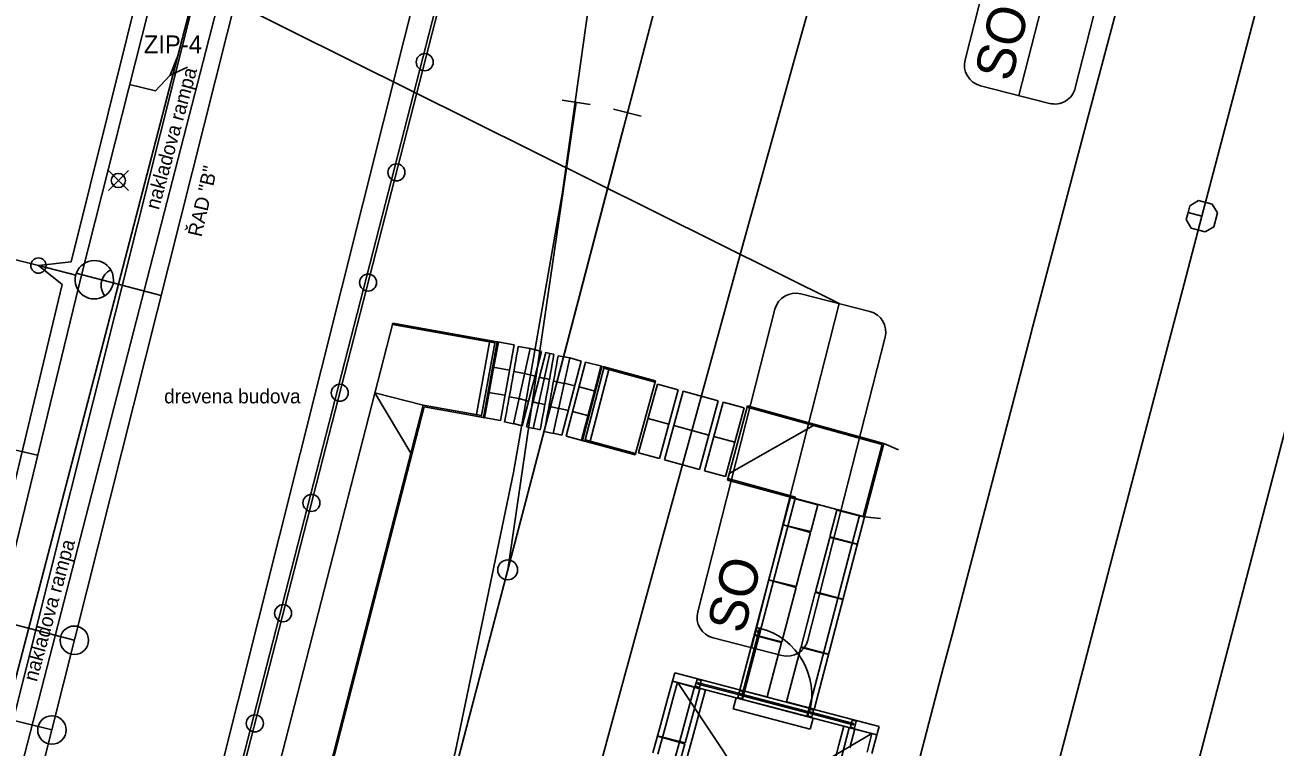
# Model space of a CAD drawing. Extents: x -733601 to -733291, y -1137892 to -1137187.
# Drawn here: x -733445.37 to -733401.43, y -1137582.33 to -1137556.95 of the extents above; entities that cross this region are included whole.
import ezdxf

# ---------------------------------------------------------------- set-up
doc = ezdxf.new("R2010")
doc.units = 0
for name, color, linetype in [('Default', 7, 'Continuous'), ('SIT_PROJ', 7, 'Continuous'), ('SIT_PUV_BUS', 7, 'Continuous'), ('SIT_PUV_ZELEZNICE', 7, 'Continuous')]:
    doc.layers.add(name, color=color, linetype=linetype)

# ---------------------------------------------------------------- blocks, each defined once
blk = doc.blocks.new('novy_s_2r')
at = {"layer": 'Default'}
for p in [(502.569, 387.82), (502.559, 384.813)]:
    blk.add_line(p, (502.564, 386.316), dxfattribs=at)
blk.add_circle((502.564, 386.316), 0.298, dxfattribs=at)
blk.add_circle((502.564, 386.316), 0.298, dxfattribs=at)
blk.add_circle((502.564, 386.316), 0.298, dxfattribs=at)
blk.add_circle((502.564, 386.316), 0.298, dxfattribs=at)
for centre, radius, start, end in [((502.571, 388.57), 0.75, 46.9837, 135.4673), ((502.571, 388.57), 0.75, 46.9837, 135.4673), ((502.571, 388.57), 0.75, 135.4683, 46.9828), ((502.55, 389.547), 0.684, 221.2842, 321.1668), ((502.55, 389.547), 0.684, 221.2842, 321.1668), ((502.556, 384.063), 0.75, 315.4683, 226.9828), ((502.577, 383.086), 0.684, 41.2842, 141.1668), ((502.577, 383.086), 0.684, 41.2842, 141.1668), ((502.556, 384.063), 0.75, 226.9837, 315.4673), ((502.556, 384.063), 0.75, 226.9837, 315.4673)]:
    blk.add_arc(centre, radius, start, end, dxfattribs=at)
blk = doc.blocks.new('VY1')
at = {"layer": 'Default'}
for q in [(-50, 275), (50, 275), (0, 0)]:
    blk.add_line((0, 150), q, dxfattribs=at)
blk = doc.blocks.new('POINT_DISPLAY')
at = {"layer": 'Default'}
for p, q in [((-0.7, -0.7), (0.7, 0.7)), ((-0.7, 0.7), (0.7, -0.7))]:
    blk.add_line(p, q, dxfattribs=at)
blk.add_circle((0, 0), 0.5, dxfattribs=at)
blk = doc.blocks.new('vytyc_bod_MP')
at = {"layer": 'Default'}
blk.add_blockref('POINT_DISPLAY', (0, 0), dxfattribs=at)
blk = doc.blocks.new('T_PS_1_1_6')
at = {"layer": 'Default'}
blk.add_line((-12.486, 3.717), (12.486, 3.717), dxfattribs=at)
for points in [[(10.986, 8), (-10.986, 8)], [(-12.486, 6.5), (-12.486, 1.5)], [(12.486, 1.5), (12.486, 6.5)], [(-10.986, 0), (10.986, 0)]]:
    blk.add_lwpolyline(points, dxfattribs=at)
for centre, start, end in [((-10.986, 6.5), 90, 180), ((10.986, 6.5), 0, 90), ((-10.986, 1.5), 180, 270), ((10.986, 1.5), 270, 360)]:
    blk.add_arc(centre, 1.5, start, end, dxfattribs=at)
blk.add_text('SO', height=2.7, dxfattribs=at).set_placement((-11.75, 4.466))
blk = doc.blocks.new('T_PS_1_1_7')
at = {"layer": 'Default'}
blk.add_line((-12.486, 3.717), (12.486, 3.717), dxfattribs=at)
for points in [[(10.986, 8), (-10.986, 8)], [(-12.486, 6.5), (-12.486, 1.5)], [(12.486, 1.5), (12.486, 6.5)], [(-10.986, 0), (10.986, 0)]]:
    blk.add_lwpolyline(points, dxfattribs=at)
for centre, start, end in [((-10.986, 6.5), 90, 180), ((10.986, 6.5), 0, 90), ((-10.986, 1.5), 180, 270), ((10.986, 1.5), 270, 360)]:
    blk.add_arc(centre, 1.5, start, end, dxfattribs=at)
blk.add_text('SO', height=2.7, dxfattribs=at).set_placement((-11.75, 4.466))

msp = doc.modelspace()

# ---------------------------------------------------------------- linework, layer by layer
at = {"layer": 'SIT_PROJ'}
msp.add_line((-733440.281, -1137593.122), (-733430.325, -1137554.381), dxfattribs=at)
for points in [[(-733457.917, -1137622.364), (-733458.777, -1137620.095), (-733456.339, -1137614.218), (-733457.273, -1137613.333), (-733455.913, -1137612.939), (-733454.69, -1137608.9), (-733452.562, -1137600.661), (-733449.967, -1137590.732), (-733451.007, -1137589.721), (-733449.679, -1137589.475), (-733444.067, -1137566.075), (-733444.902, -1137565.405), (-733443.754, -1137565.269), (-733437.875, -1137541.673), (-733438.793, -1137541.042), (-733437.71, -1137541.027), (-733436.525, -1137536.63), (-733452.133, -1137532.662), (-733452.807, -1137531.541)], [(-733456.299, -1137623.235), (-733433.573, -1137532.72)], [(-733432.51, -1137534.385), (-733444.427, -1137581.731), (-733459.039, -1137578.132)], [(-733429.102, -1137545.713), (-733449.631, -1137627.477)], [(-733457.917, -1137622.364), (-733458.523, -1137621.757), (-733455.851, -1137614.377), (-733455.422, -1137613.019), (-733451.725, -1137599.481), (-733449.522, -1137590.912), (-733449.164, -1137589.482), (-733443.392, -1137565.741), (-733438.875, -1137547.904)], [(-733440.387, -1137554.973), (-733416.748, -1137566.741), (-733416.748, -1137566.741)], [(-733441.694, -1137559.038), (-733440.78, -1137559.259)], [(-733443.578, -1137565.675), (-733440.587, -1137566.455)], [(-733448.861, -1137571.168), (-733444.931, -1137572.072)], [(-733446.608, -1137577.804), (-733443.64, -1137578.577)], [(-733454.604, -1137622.264), (-733444.427, -1137581.731)]]:
    msp.add_lwpolyline(points, dxfattribs=at)
for centre, radius in [((-733431.321, -1137558.255), 0.3), ((-733432.316, -1137562.129), 0.3), ((-733433.312, -1137566.003), 0.3), ((-733434.307, -1137569.877), 0.3), ((-733435.303, -1137573.751), 0.3), ((-733436.299, -1137577.626), 0.3), ((-733443.64, -1137578.578), 0.5), ((-733444.427, -1137581.732), 0.5), ((-733437.294, -1137581.5), 0.3)]:
    msp.add_circle(centre, radius, dxfattribs=at)
at = {"layer": 'SIT_PUV_BUS'}
for p, q in [((-733437.84, -1137549.69), (-733442.47, -1137567.55)), ((-733445.62, -1137583.47), (-733437, -1137550.03)), ((-733429.79, -1137551.88), (-733440.4, -1137593.2)), ((-733442.47, -1137567.55), (-733446.56, -1137583.19))]:
    msp.add_line(p, q, dxfattribs=at)
at = {"layer": 'SIT_PUV_ZELEZNICE'}
for p, q in [((-733404.487, -1137563.543), (-733404.423, -1137563.301)), ((-733404.423, -1137563.301), (-733404.117, -1137563.123)), ((-733404.117, -1137563.123), (-733403.634, -1137563.25)), ((-733403.634, -1137563.25), (-733403.456, -1137563.556)), ((-733404.55, -1137563.785), (-733404.487, -1137563.543)), ((-733404.003, -1137563.67), (-733404.487, -1137563.543)), ((-733403.456, -1137563.556), (-733403.583, -1137564.039)), ((-733404.372, -1137564.09), (-733404.55, -1137563.785)), ((-733403.889, -1137564.217), (-733404.372, -1137564.09)), ((-733403.583, -1137564.039), (-733403.889, -1137564.217)), ((-733437.941, -1137588.784), (-733432.439, -1137567.425)), ((-733428.859, -1137568.124), (-733432.452, -1137567.473)), ((-733428.769, -1137568.089), (-733432.439, -1137567.425)), ((-733429.028, -1137568.042), (-733429.509, -1137570.699)), ((-733428.85, -1137568.074), (-733429.332, -1137570.731)), ((-733428.769, -1137568.089), (-733429.25, -1137570.746)), ((-733428.757, -1137568.091), (-733429.239, -1137570.748)), ((-733429.028, -1137568.042), (-733428.732, -1137568.096)), ((-733428.769, -1137568.089), (-733428.85, -1137568.074)), ((-733428.757, -1137568.091), (-733428.178, -1137568.196)), ((-733428.178, -1137568.196), (-733428.66, -1137570.853)), ((-733428.205, -1137570.973), (-733427.618, -1137568.321)), ((-733427.618, -1137568.321), (-733428.031, -1137568.248)), ((-733427.213, -1137568.427), (-733427.618, -1137568.321)), ((-733426.922, -1137568.497), (-733427.506, -1137571.135)), ((-733426.922, -1137568.497), (-733427.064, -1137568.46)), ((-733426.922, -1137568.497), (-733426.779, -1137568.522)), ((-733426.224, -1137568.655), (-733426.635, -1137568.582)), ((-733428.339, -1137569.082), (-733428.918, -1137568.977)), ((-733426.811, -1137571.307), (-733426.224, -1137568.655)), ((-733426.353, -1137571.409), (-733425.669, -1137568.797)), ((-733425.819, -1137568.761), (-733426.224, -1137568.655)), ((-733425.784, -1137571.558), (-733425.1, -1137568.946)), ((-733425.773, -1137571.561), (-733425.089, -1137568.949)), ((-733425.692, -1137571.582), (-733425.008, -1137568.97)), ((-733425.669, -1137568.797), (-733425.1, -1137568.946)), ((-733425.518, -1137571.628), (-733424.834, -1137569.016)), ((-733424.834, -1137569.016), (-733425.124, -1137568.94)), ((-733425.089, -1137568.949), (-733425.008, -1137568.97)), ((-733423.225, -1137569.5), (-733425.021, -1137569.018)), ((-733423.212, -1137569.452), (-733425.008, -1137568.97)), ((-733428.188, -1137569.134), (-733427.813, -1137569.202)), ((-733427.441, -1137569.298), (-733427.813, -1137569.2)), ((-733427.117, -1137569.376), (-733427.292, -1137569.33)), ((-733426.937, -1137569.408), (-733427.115, -1137569.369)), ((-733426.793, -1137569.468), (-733426.422, -1137569.55)), ((-733423.922, -1137572.057), (-733423.212, -1137569.452)), ((-733431.375, -1137570.31), (-733433.07, -1137569.874)), ((-733433.07, -1137569.874), (-733431.812, -1137572.005)), ((-733428.499, -1137569.967), (-733429.078, -1137569.863)), ((-733426.047, -1137569.632), (-733426.418, -1137569.534)), ((-733425.897, -1137569.668), (-733425.328, -1137569.817)), ((-733423.8, -1137571.988), (-733423.142, -1137569.576)), ((-733423.142, -1137569.576), (-733422.409, -1137569.776)), ((-733423.067, -1137572.188), (-733422.409, -1137569.776)), ((-733422.892, -1137572.236), (-733422.236, -1137569.824)), ((-733422.236, -1137569.824), (-733421.001, -1137570.159)), ((-733435.499, -1137586.32), (-733431.375, -1137570.31)), ((-733435.451, -1137586.332), (-733431.338, -1137570.368)), ((-733429.323, -1137570.682), (-733431.375, -1137570.31)), ((-733429.25, -1137570.746), (-733431.338, -1137570.368)), ((-733428.349, -1137570.02), (-733428.008, -1137570.082)), ((-733427.669, -1137570.169), (-733428.007, -1137570.08)), ((-733427.312, -1137570.256), (-733427.519, -1137570.201)), ((-733427.098, -1137570.294), (-733427.31, -1137570.247)), ((-733426.954, -1137570.354), (-733426.616, -1137570.428)), ((-733421.657, -1137572.572), (-733421.001, -1137570.159)), ((-733421.482, -1137572.619), (-733420.828, -1137570.206)), ((-733420.095, -1137570.405), (-733420.828, -1137570.206)), ((-733419.973, -1137570.339), (-733420.68, -1137572.945)), ((-733419.973, -1137570.339), (-733415.177, -1137571.656)), ((-733429.509, -1137570.699), (-733429.214, -1137570.753)), ((-733429.25, -1137570.746), (-733429.332, -1137570.731)), ((-733428.66, -1137570.853), (-733429.239, -1137570.748)), ((-733426.275, -1137570.502), (-733426.613, -1137570.414)), ((-733426.125, -1137570.538), (-733425.556, -1137570.687)), ((-733423.471, -1137570.782), (-733422.738, -1137570.982)), ((-733420.749, -1137572.818), (-733420.095, -1137570.405)), ((-733419.986, -1137570.388), (-733415.238, -1137571.691)), ((-733428.512, -1137570.905), (-733428.205, -1137570.973)), ((-733427.897, -1137571.039), (-733428.202, -1137570.959)), ((-733427.506, -1137571.135), (-733427.747, -1137571.072)), ((-733427.261, -1137571.179), (-733427.504, -1137571.125)), ((-733427.117, -1137571.239), (-733426.811, -1137571.307)), ((-733422.564, -1137571.03), (-733421.329, -1137571.366)), ((-733420.617, -1137572.714), (-733417.656, -1137571.027)), ((-733426.503, -1137571.373), (-733426.808, -1137571.293)), ((-733425.784, -1137571.558), (-733426.353, -1137571.409)), ((-733425.518, -1137571.628), (-733425.809, -1137571.551)), ((-733425.773, -1137571.561), (-733425.692, -1137571.582)), ((-733425.692, -1137571.582), (-733423.922, -1137572.057)), ((-733425.68, -1137571.534), (-733423.909, -1137572.008)), ((-733420.422, -1137571.611), (-733421.155, -1137571.412)), ((-733415.857, -1137574.24), (-733415.177, -1137571.656)), ((-733414.668, -1137571.878), (-733415.177, -1137571.656)), ((-733423.8, -1137571.988), (-733423.067, -1137572.188)), ((-733415.905, -1137574.228), (-733415.238, -1137571.691)), ((-733422.892, -1137572.236), (-733421.657, -1137572.572)), ((-733420.749, -1137572.818), (-733421.482, -1137572.619)), ((-733420.68, -1137572.945), (-733418.467, -1137573.553)), ((-733420.667, -1137572.897), (-733418.281, -1137573.552)), ((-733420.248, -1137580.323), (-733418.467, -1137573.553)), ((-733420.074, -1137580.369), (-733418.281, -1137573.552)), ((-733418.469, -1137573.558), (-733417.504, -1137573.822)), ((-733418.467, -1137573.553), (-733415.857, -1137574.24)), ((-733417.504, -1137573.822), (-733417.751, -1137574.76)), ((-733417.81, -1137580.964), (-733416.031, -1137574.195)), ((-733417.636, -1137581.01), (-733415.857, -1137574.24)), ((-733416.828, -1137574.001), (-733417.074, -1137574.939)), ((-733415.858, -1137574.245), (-733416.828, -1137574.001)), ((-733415.301, -1137574.297), (-733415.857, -1137574.24)), ((-733418.723, -1137574.525), (-733417.759, -1137574.789)), ((-733417.751, -1137574.76), (-733418.721, -1137574.515)), ((-733417.759, -1137574.789), (-733418.26, -1137576.694)), ((-733417.082, -1137574.968), (-733417.583, -1137576.873)), ((-733416.112, -1137575.212), (-733417.082, -1137574.968)), ((-733417.074, -1137574.939), (-733416.11, -1137575.203)), ((-733419.232, -1137576.459), (-733418.267, -1137576.723)), ((-733418.26, -1137576.694), (-733419.229, -1137576.45)), ((-733418.267, -1137576.723), (-733418.768, -1137578.629)), ((-733417.59, -1137576.902), (-733418.091, -1137578.807)), ((-733416.621, -1137577.147), (-733417.59, -1137576.902)), ((-733417.583, -1137576.873), (-733416.618, -1137577.137)), ((-733419.555, -1137578.176), (-733420.166, -1137580.5)), ((-733420.119, -1137580.512), (-733419.508, -1137578.188)), ((-733419.74, -1137578.394), (-733418.776, -1137578.658)), ((-733418.768, -1137578.629), (-733419.738, -1137578.384)), ((-733418.776, -1137578.658), (-733419.277, -1137580.563)), ((-733418.099, -1137578.836), (-733418.6, -1137580.742)), ((-733417.129, -1137579.081), (-733418.099, -1137578.836)), ((-733418.091, -1137578.807), (-733417.127, -1137579.071)), ((-733422.613, -1137580.017), (-733421.651, -1137580.289)), ((-733422.612, -1137580.012), (-733420.15, -1137580.659)), ((-733422.533, -1137579.722), (-733420.074, -1137580.369)), ((-733419.7, -1137584.149), (-733422.437, -1137580.057)), ((-733421.651, -1137580.289), (-733422.168, -1137582.19)), ((-733421.714, -1137580.119), (-733420.215, -1137580.513)), ((-733420.202, -1137580.466), (-733421.702, -1137580.072)), ((-733419.277, -1137580.563), (-733420.246, -1137580.318)), ((-733420.074, -1137580.369), (-733420.15, -1137580.659)), ((-733420.074, -1137580.369), (-733417.81, -1137580.964)), ((-733420.372, -1137580.6), (-733420.474, -1137580.987)), ((-733417.664, -1137581.312), (-733420.372, -1137580.6)), ((-733420.179, -1137580.651), (-733417.858, -1137581.262)), ((-733417.887, -1137581.254), (-733420.15, -1137580.659)), ((-733420.149, -1137580.53), (-733417.824, -1137581.141)), ((-733417.812, -1137581.094), (-733420.137, -1137580.483)), ((-733418.6, -1137580.742), (-733417.635, -1137581.006)), ((-733420.474, -1137580.987), (-733417.766, -1137581.699)), ((-733417.81, -1137580.964), (-733417.887, -1137581.254)), ((-733417.887, -1137581.254), (-733415.427, -1137581.901)), ((-733417.81, -1137580.964), (-733415.351, -1137581.61)), ((-733417.766, -1137581.699), (-733417.664, -1137581.312)), ((-733417.758, -1137581.158), (-733416.259, -1137581.552)), ((-733416.247, -1137581.505), (-733417.746, -1137581.111)), ((-733416.398, -1137581.663), (-733416.895, -1137583.569)), ((-733415.428, -1137581.906), (-733416.398, -1137581.663)), ((-733423.138, -1137581.946), (-733422.176, -1137582.218)), ((-733422.168, -1137582.19), (-733423.135, -1137581.937)), ((-733422.176, -1137582.218), (-733422.692, -1137584.119)), ((-733415.601, -1137581.855), (-733419.575, -1137584.182))]:
    msp.add_line(p, q, dxfattribs=at)
for points in [[(-733432.613, -1137592.177), (-733430.241, -1137582.464), (-733428.195, -1137572.675), (-733426.476, -1137562.825), (-733425.101, -1137553.045), (-733425.086, -1137552.922), (-733424.525, -1137548.394), (-733423.804, -1137543.005), (-733422.199, -1137533.135), (-733420.237, -1137523.33), (-733417.92, -1137513.602), (-733417.278, -1137511.157), (-733415.349, -1137503.939), (-733412.766, -1137494.278), (-733410.183, -1137484.617), (-733407.6, -1137474.957), (-733405.017, -1137465.296), (-733402.434, -1137455.636), (-733401.342, -1137451.549), (-733399.798, -1137445.99), (-733397.493, -1137438.369), (-733396.877, -1137436.426), (-733393.987, -1137427.309)], [(-733424.195, -1137560.031), (-733423.136, -1137555.989), (-733422.64, -1137554.102), (-733420.028, -1137544.45), (-733419.6, -1137542.91), (-733417.303, -1137534.828), (-733414.464, -1137525.239), (-733413.695, -1137522.711), (-733413.646, -1137522.55), (-733411.495, -1137515.69), (-733408.347, -1137506.199), (-733407.141, -1137502.714), (-733405.019, -1137496.769), (-733401.513, -1137487.404), (-733399.59, -1137482.49), (-733397.847, -1137478.1), (-733394.158, -1137468.806), (-733394.03, -1137468.485), (-733390.544, -1137459.482), (-733387.094, -1137450.096), (-733383.809, -1137440.651), (-733380.689, -1137431.15), (-733380.109, -1137429.318)], [(-733408.191, -1137579.632), (-733407.168, -1137575.72), (-733404.629, -1137566.048), (-733404.003, -1137563.67), (-733402.076, -1137556.379), (-733400.028, -1137548.693), (-733399.499, -1137546.716), (-733396.898, -1137537.061), (-733394.522, -1137528.325), (-733394.273, -1137527.412), (-733391.623, -1137517.769), (-733389.167, -1137508.912), (-733388.95, -1137508.133), (-733388.909, -1137507.986), (-733386.266, -1137498.5), (-733383.849, -1137489.821)], [(-733424.808, -1137581.736), (-733423.595, -1137577.27), (-733420.948, -1137567.626), (-733420.168, -1137564.801), (-733418.278, -1137557.99), (-733415.583, -1137548.36), (-733412.864, -1137538.736), (-733410.121, -1137529.12), (-733408.737, -1137524.299), (-733407.354, -1137519.51), (-733404.564, -1137509.907), (-733401.749, -1137500.312), (-733398.91, -1137490.723)], [(-733412.782, -1137578.384), (-733410.545, -1137569.839), (-733410.013, -1137567.818), (-733410.012, -1137567.811), (-733407.996, -1137560.169), (-733405.429, -1137550.505), (-733403.156, -1137542.021), (-733402.84, -1137540.845), (-733400.227, -1137531.193), (-733399.104, -1137527.074), (-733397.59, -1137521.547), (-733394.93, -1137511.907), (-733392.245, -1137502.274), (-733389.536, -1137492.648)], [(-733428.404, -1137576.104), (-733425.996, -1137559.664)], [(-733426.491, -1137559.592), (-733425.501, -1137559.737)], [(-733432.613, -1137592.178), (-733428.404, -1137576.104), (-733424.195, -1137560.031)], [(-733424.679, -1137559.904), (-733423.711, -1137560.157)], [(-733432.612, -1137592.177), (-733430.242, -1137583.123), (-733427.708, -1137573.449), (-733425.176, -1137563.776), (-733424.321, -1137560.514)], [(-733428.732, -1137568.096), (-733428.742, -1137568.153), (-733428.921, -1137569.137), (-733429.099, -1137570.121), (-733429.214, -1137570.753)], [(-733427.897, -1137571.039), (-733427.213, -1137568.427)], [(-733427.747, -1137571.072), (-733427.064, -1137568.46)], [(-733426.503, -1137571.373), (-733425.819, -1137568.761)], [(-733425.809, -1137571.551), (-733425.794, -1137571.495), (-733425.541, -1137570.528), (-733425.287, -1137569.561), (-733425.124, -1137568.94)], [(-733405.605, -1137588.525), (-733403.077, -1137578.85), (-733400.54, -1137569.177)], [(-733459.36, -1137757.582), (-733458.338, -1137753.729), (-733455.783, -1137744.061), (-733453.237, -1137734.391), (-733450.698, -1137724.719), (-733448.167, -1137715.044), (-733445.645, -1137705.368), (-733443.13, -1137695.689), (-733440.624, -1137686.008), (-733440.158, -1137684.204), (-733438.123, -1137676.326), (-733435.622, -1137666.644), (-733433.121, -1137656.962), (-733430.62, -1137647.279), (-733428.119, -1137637.597), (-733425.618, -1137627.915), (-733423.422, -1137619.411), (-733423.117, -1137618.233), (-733420.616, -1137608.551), (-733418.11, -1137598.87), (-733415.599, -1137589.19), (-733413.078, -1137579.513), (-733412.782, -1137578.384)], [(-733453.981, -1137756.29), (-733452.315, -1137749.966), (-733449.778, -1137740.293), (-733447.253, -1137730.617), (-733444.741, -1137720.938), (-733443.633, -1137716.651), (-733442.239, -1137711.256), (-733439.738, -1137701.574), (-733437.237, -1137691.892), (-733434.736, -1137682.209), (-733432.235, -1137672.527), (-733429.735, -1137662.844), (-733427.234, -1137653.162), (-733424.733, -1137643.48), (-733422.232, -1137633.798), (-733419.731, -1137624.116), (-733417.23, -1137614.434), (-733415.895, -1137609.267), (-733414.728, -1137604.752), (-733412.218, -1137595.072), (-733409.698, -1137585.394), (-733408.191, -1137579.632)], [(-733423.297, -1137582.532), (-733423.035, -1137581.567), (-733422.773, -1137580.603), (-733422.612, -1137580.012), (-733422.533, -1137579.722)], [(-733423.124, -1137582.579), (-733422.861, -1137581.615), (-733422.599, -1137580.65), (-733422.437, -1137580.057)], [(-733422.525, -1137582.742), (-733422.263, -1137581.777), (-733422.001, -1137580.813), (-733421.838, -1137580.215)], [(-733422.139, -1137582.847), (-733421.877, -1137581.882), (-733421.615, -1137580.918), (-733421.451, -1137580.317)], [(-733469.582, -1137755.14), (-733468.663, -1137751.534), (-733466.195, -1137741.843), (-733463.726, -1137732.153), (-733461.257, -1137722.462), (-733458.789, -1137712.772), (-733456.32, -1137703.081), (-733453.852, -1137693.391), (-733451.383, -1137683.701), (-733451.044, -1137682.371), (-733448.914, -1137674.01), (-733446.443, -1137664.32), (-733443.966, -1137654.632), (-733441.48, -1137644.946), (-733438.982, -1137635.263), (-733436.47, -1137625.584), (-733433.94, -1137615.909), (-733431.39, -1137606.239), (-733431.038, -1137604.913), (-733428.815, -1137596.577), (-733426.217, -1137586.92), (-733424.808, -1137581.736)], [(-733417.011, -1137583.219), (-733416.759, -1137582.254), (-733416.588, -1137581.596)], [(-733416.372, -1137582.355), (-733416.201, -1137581.697)], [(-733415.598, -1137582.556), (-733415.427, -1137581.901), (-733415.351, -1137581.61)], [(-733415.772, -1137582.511), (-733415.601, -1137581.855)]]:
    msp.add_lwpolyline(points, dxfattribs=at)
for points in [[(-733419.57, -1137578.413), (-733419.715, -1137578.375), (-733419.651, -1137578.133), (-733419.506, -1137578.171)], [(-733421.667, -1137580.235), (-733421.812, -1137580.197), (-733421.748, -1137579.955), (-733421.603, -1137579.993)], [(-733420.168, -1137580.628), (-733420.313, -1137580.59), (-733420.249, -1137580.349), (-733420.104, -1137580.387)], [(-733417.711, -1137581.275), (-733417.856, -1137581.237), (-733417.793, -1137580.995), (-733417.648, -1137581.033)], [(-733416.212, -1137581.669), (-733416.357, -1137581.63), (-733416.294, -1137581.389), (-733416.149, -1137581.427)]]:
    msp.add_lwpolyline(points, close=True, dxfattribs=at)
for centre, radius in [((-733428.404, -1137576.104), 0.35), ((-733419.61, -1137578.272), 0.0241), ((-733419.531, -1137578.182), 0.0241), ((-733421.708, -1137580.095), 0.0241), ((-733420.209, -1137580.489), 0.0241), ((-733420.142, -1137580.506), 0.0241), ((-733420.142, -1137580.506), 0.0241), ((-733417.818, -1137581.117), 0.0241), ((-733417.752, -1137581.135), 0.0241), ((-733416.253, -1137581.529), 0.0241)]:
    msp.add_circle(centre, radius, dxfattribs=at)
for centre, radius, start, end in [((-733722.828, -1137516.184), 299.36, 349.46747, 349.98427), ((-733722.828, -1137516.184), 300.64, 349.45979, 349.97436), ((-733722.828, -1137516.184), 300.793, 349.45356, 349.96786), ((-733420.142, -1137580.506), 2.428, 345.2735, 74.9866)]:
    msp.add_arc(centre, radius, start, end, dxfattribs=at)

# ---------------------------------------------------------------- block references
at = {"layer": 'SIT_PROJ'}
for name, p, xscale, yscale, rotation in [('T_PS_1_1_6', (-733407.092, -1137553.839), 0.4999999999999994, 0.4999999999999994, 75.68569569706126), ('VY1', (-733440.78, -1137559.259), 0.005, 0.004999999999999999, -43.302577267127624), ('novy_s_2r', (-733217.423, -1138088.588), 0.9000000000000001, 0.8999999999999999, 75.95014741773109), ('T_PS_1_1_7', (-733416.491, -1137573.25), 0.4999999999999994, 0.49999999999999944, 75.68569569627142)]:
    msp.add_blockref(name, p, dxfattribs=dict(at, xscale=xscale, yscale=yscale, rotation=rotation))
at = {"layer": 'SIT_PROJ', "xscale": 0.5, "yscale": 0.5}
msp.add_blockref('vytyc_bod_MP', (-733442.089, -1137562.413), dxfattribs=at)

# ---------------------------------------------------------------- texts
at = {"layer": 'SIT_PROJ'}
for s, height, rotation, p in [('ZIP-4', 0.625, 360, (-733441.196, -1137557.941)), ('ŘAD "B"', 0.5, 77.0268, (-733439.17, -1137564.424))]:
    msp.add_text(s, height=height, rotation=rotation, dxfattribs=at).set_placement(p)
at = {"layer": 'SIT_PUV_BUS'}
for p in [(-733440.67, -1137563.47), (-733444.96, -1137580.06)]:
    msp.add_text('nakladova rampa', height=0.5, rotation=74.7, dxfattribs=at).set_placement(p)
msp.add_text('drevena budova', height=0.5, dxfattribs=at).set_placement((-733440.48, -1137570.25))

doc.saveas('drawing.dxf')
